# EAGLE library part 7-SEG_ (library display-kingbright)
Kingbright 14.2mm (0.56 INCH) SINGLE DIGIT NUMERIC DUISPLAY Source: SA56-11EWA(Ver1189471036.pdf
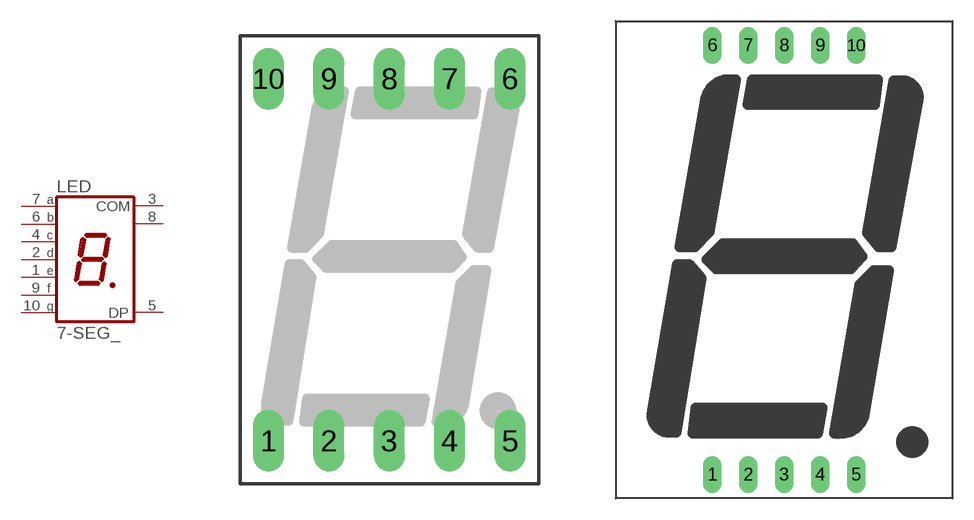
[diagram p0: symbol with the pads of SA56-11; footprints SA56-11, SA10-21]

Designator prefix LED

## 7-SEG_SA56-11 (OC_FARNELL: unknown; OC_NEWARK: unknown)  [SA56-11]
1  E  pas
2  D  pas
3  COM  pas
4  C  pas
5  DP  pas
6  B  pas
7  A  pas
8  COM  pas
9  F  pas
10  G  pas

## 7-SEG_SA10-21 (OC_FARNELL: unknown; OC_NEWARK: unknown)  [SA10-21]
Pads as for SA56-11

## 7-SEG_SA18-11 (OC_FARNELL: unknown; OC_NEWARK: unknown)  [SA18-11]
1  COM  pas
2  E  pas
3  D  pas
4  C  pas
5  COM  pas
6  B  pas
7  A  pas
8  DP  pas
9  F  pas
10  G  pas

## 7-SEG_SA52-11 (OC_FARNELL: unknown; OC_NEWARK: unknown)  [SA52-11]
Pads as for SA56-11

## 7-SEG_SA39-11SRWA (OC_FARNELL: unknown; OC_NEWARK: unknown)  [SA39-11SRWA]
1  G  pas
2  F  pas
3  COM  pas
4  E  pas
5  D  pas
6  DP  pas
7  C  pas
8  COM  pas
9  B  pas
10  A  pas

## Footprint SA56-11 (pad centres in mm)
Kingbright 14.2mm (0.56 INCH) SINGLE DIGIT NUMERIC DUISPLAY Source: SA56-11EWA(Ver1189471036.pdf
drill 0.8 long: 1 -5.08,-7.62; 2 -2.54,-7.62; 3 0,-7.62; 4 2.54,-7.62; 5 5.08,-7.62; 6 5.08,7.62; 7 2.54,7.62; 8 0,7.62; 9 -2.54,7.62; 10 -5.08,7.62

## Footprint SA10-21 (pad centres in mm)
25.4mm (1.0 INCH) SINGLE DIGIT NUMERIC DISPLAY Source: SA10-21EWA(Ver1189472078.10).pdf
drill 0.8 long: 1 -5.08,-15.2; 2 -2.54,-15.2; 3 0,-15.2; 4 2.54,-15.2; 5 5.08,-15.2; 6 -5.08,15.2; 7 -2.54,15.2; 8 0,15.2; 9 2.54,15.2; 10 5.08,15.2

## Footprint SA18-11 (pad centres in mm)
44.5mm (1.75INCH) SINGLE DIGIT NUMERIC DISPLAY Source: SA18-11EWA(Ver1189472866.5).pdf
drill 0.7 pad 1.422 long: 1 -5.08,-24.13; 2 -2.54,-24.13; 3 0,-24.13; 4 2.54,-24.13; 5 5.08,-24.13; 6 -5.08,24.13; 7 -2.54,24.13; 8 0,24.13; 9 2.54,24.13; 10 5.08,24.13

## Footprint SA52-11 (pad centres in mm)
13.2mm (0.52INCH) SINGLE DIGIT NUMERIC DISPLAY Source: http://www.kingbright.com/manager/upload/pdf/SA52-11EWA(Ver1195708215.10)
drill 0.8 round: 1 -5.08,-7.62; 2 -2.54,-7.62; 3 0,-7.62; 4 2.54,-7.62; 5 5.08,-7.62; 6 5.08,7.62; 7 2.54,7.62; 8 0,7.62; 9 -2.54,7.62; 10 -5.08,7.62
